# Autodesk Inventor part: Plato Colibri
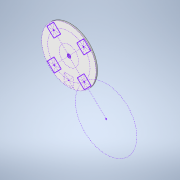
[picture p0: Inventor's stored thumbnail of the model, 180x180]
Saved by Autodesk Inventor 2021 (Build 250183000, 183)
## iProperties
Created: 2021-03
Part Number: Plato Colibri
Material: Genérico
Document SubType Name: Modeling
Designer: ATOUZA
Density: 1 g/cm^3
Appearance: Valor por defecto
Author: ATOUZA
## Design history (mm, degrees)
sketch "Boceto1"
  geometry: L1 (0, 0)-(136.919, -132.703); L2 (-17.5, -95.3)-(17.5, -95.3); L3 (17.5, -95.3)-(17.5, -60.3); L4 (17.5, -60.3)-(-17.5, -60.3); L5 (-17.5, -60.3)-(-17.5, -95.3); L6 (-17.5, -95.3)-(17.5, -60.3); L7 (17.5, -95.3)-(-17.5, -60.3); L8 (0, 0)-(-69.597, -71.807); L9 (0, 0)-(69.597, 71.807); L10 (0, 0)-(-71.807, 69.597); L11 (-78.892, -56.253)-(-53.759, -80.612); L12 (-53.759, -80.612)-(-29.4, -55.479); L13 (-29.4, -55.479)-(-54.533, -31.12); L14 (-54.533, -31.12)-(-78.892, -56.253); L15 (-78.892, -56.253)-(-29.4, -55.479); L16 (-53.759, -80.612)-(-54.533, -31.12); C1 r 6.4 at (0, 0) reference; C2 r 35.5 at (0, 0) reference; C3 r 3 at (136.919, -132.703) reference; C4 r 2.479 at (53.913, -56.213) reference; C5 r 6.4 at (0, 0); C6 r 100 at (0, 0); C7 r 2 at (54.146, 55.866); C8 r 2 at (-55.866, 54.146); C9 r 2 at (-54.146, -55.866); C10 r 2 at (55.866, -54.146); C11 r 2 at (-66.997, -36.796) reference; C12 r 2 at (-34.684, -68.115) reference; C13 r 2 at (36.796, -66.997) reference; C14 r 2 at (68.115, -34.684) reference; C15 r 2 at (66.997, 36.796) reference; C16 r 2 at (34.684, 68.115) reference; C17 r 2 at (-36.796, 66.997) reference; C18 r 2 at (-68.115, 34.684) reference; A1 r 112.875 centre (136.919, -132.703) between (53.913, -56.213) and (55.866, -54.146); A2 r 77.8 centre (0, 0) between (0, -77.8) and (-54.146, -55.866); A3 r 100 centre (0, 0) between (-69.597, -71.807) and (69.597, 71.807); 1 further point
  constraints: 32 end point, 10 point on circle, 9 centre point, 6 coincident, 4 midpoint, 4 parallel, 4 perpendicular, 4 point on line, 2 concentric, 1 horizontal
  dimensions: "d0" = 35 distance of L4.end L3.end; "d1" = 35 distance of L3.end L2.end; "d2" = 200 diameter of A3; "d3" = 35 distance of L11.start L11.end; "d4" = 35 distance of L12.end L11.end; "d16" = 4 diameter of C7; "d17" = 4 diameter of C8; "d18" = 4 diameter of C9; "d19" = 4 diameter of C10
extrude "Extrusión1" new body sketch "Boceto1" distance "d5" = 5.5; taper "d6" = 0 deg
sketch "Boceto2"
  geometry: L1 (0, 0)-(136.919, -132.703); L2 (-17.5, -95.3)-(17.5, -95.3); L3 (17.5, -95.3)-(17.5, -60.3); L4 (17.5, -60.3)-(-17.5, -60.3); L5 (-17.5, -60.3)-(-17.5, -95.3); L6 (-17.5, -95.3)-(17.5, -60.3); L7 (17.5, -95.3)-(-17.5, -60.3); L8 (0, 0)-(-69.597, -71.807); L9 (0, 0)-(69.597, 71.807); L10 (0, 0)-(-71.807, 69.597); L11 (-79.599, -56.264)-(-53.748, -81.319); L12 (-53.748, -81.319)-(-28.693, -55.468); L13 (-28.693, -55.468)-(-54.544, -30.413); L14 (-54.544, -30.413)-(-79.599, -56.264); L15 (-79.599, -56.264)-(-28.693, -55.468); L16 (-53.748, -81.319)-(-54.544, -30.413); L17 (-81.319, 53.748)-(-56.264, 79.599); L18 (-56.264, 79.599)-(-30.413, 54.544); L19 (-30.413, 54.544)-(-55.468, 28.693); L20 (-55.468, 28.693)-(-81.319, 53.748); L21 (-81.319, 53.748)-(-30.413, 54.544); L22 (-56.264, 79.599)-(-55.468, 28.693); L23 (53.748, 81.319)-(79.599, 56.264); L24 (79.599, 56.264)-(54.544, 30.413); L25 (54.544, 30.413)-(28.693, 55.468); L26 (28.693, 55.468)-(53.748, 81.319); L27 (53.748, 81.319)-(54.544, 30.413); L28 (79.599, 56.264)-(28.693, 55.468); L29 (56.264, -79.599)-(81.319, -53.748); L30 (81.319, -53.748)-(55.468, -28.693); L31 (55.468, -28.693)-(30.413, -54.544); L32 (30.413, -54.544)-(56.264, -79.599); L33 (56.264, -79.599)-(55.468, -28.693); L34 (81.319, -53.748)-(30.413, -54.544); C1 r 6.4 at (0, 0); C2 r 35.5 at (0, 0); C3 r 3 at (136.919, -132.703); C4 r 6.4 at (0, 0); C5 r 100 at (0, 0); C6 r 2 at (54.146, 55.866); C7 r 2 at (-55.866, 54.146); C8 r 2 at (-54.146, -55.866); C9 r 2 at (55.866, -54.146); C10 r 2 at (-55.866, 54.146) reference; C11 r 2 at (54.146, 55.866) reference; A1 r 77.8 centre (0, 0) between (0, -77.8) and (-54.146, -55.866); A2 r 100 centre (0, 0) between (-69.597, -71.807) and (69.597, 71.807); 3 further points
  constraints: 68 end point, 11 centre point, 11 parallel, 10 midpoint, 9 perpendicular, 8 point on circle, 6 coincident, 4 point on line, 2 concentric, 1 horizontal, 3 other
  dimensions: "d7" = 35 distance of L4.end L3.end; "d8" = 35 distance of L3.end L2.end; "d9" = 200 diameter of A2; "d10" = 36 distance of L11.start L11.end; "d11" = 36 distance of L12.end L11.end; "d12" = 4 diameter of C6; "d13" = 4 diameter of C7; "d14" = 4 diameter of C8; "d15" = 4 diameter of C9; "d20" = 36 distance of L18.end L19.end; "d21" = 36 distance of L17.end L18.end; "d22" = 155.59995 diameter of A1; "d23" = 36 distance of L24.end L25.end; "d24" = 36 distance of L23.end L24.end; "d25" = 36 distance of L31.end L30.end; "d26" = 36 distance of L30.end L29.end
node "Sólido1"
node "Referencia1"
node "Referencia2"
node "Referencia3"
node "Referencia4"
node "Referencia5"
node "Referencia6"
node "Referencia7"
node "Referencia8"
node "Referencia9"
node "Referencia10"
node "Referencia11"
node "Referencia12"
